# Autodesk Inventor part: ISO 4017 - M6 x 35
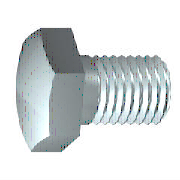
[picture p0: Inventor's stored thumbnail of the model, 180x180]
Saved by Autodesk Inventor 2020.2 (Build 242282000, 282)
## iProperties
Manager: www.cadconsulting.pl
Company: Fabian Stasiak CAD Consulting
Created: 2010-02
Part Number: ISO 4017 - M6 x 35
Material: Stal nierdzewna, 440C
Description: Wkręty z łbem sześciokątnym
Document SubType Name: Modeling
Standard: ISO 4017
Designer: F.Stasiak
Standard Revision: Third edition 1999-08-15
Standards Organization: ISO
Language: pl-PL
Size Designation: M6 x 35
Categories: <MemberInstance><Categories><Category DisplayName="Mocowania" InternalName="e4da775c-781d-43d5-af7c-5136215cf5a6" Mnemonic="FSTN"><Category DisplayName="Śruby"
Density: 7.75 g/cm^3
Appearance: Metal-Stal
IsCustomPart: 0
Author: F.Stasiak
Subject: Zbiór ćwiczeń. Autodesk Inventor 2020. Kurs podstawowy
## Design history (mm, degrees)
sketch "Sketch1"
  geometry: L1 (0, 4.44)-(0, 3); L2 (3, 3)-(35, 3); L3 (35, 3)-(35, 0); L4 (35, 0)-(-0.5, 0); L5 (-7.6, 0)-(42.1, 0) reference; L6 (-0.5, 0)-(-0.5, 4.44); L7 (-0.5, 4.44)-(0, 4.44); L8 (3, 3)-(2.386, 3); L9 (2.386, 3)-(0, 3); L10 (0, -0.888)-(0, 5.328) reference
  constraints: 16 end point, 2 collinear, 2 perpendicular, 1 parallel
  dimensions: "d0" = 35 distance between parallel lines of L3 L1 (= NLG); "d1" = 32 distance from line of L2.start L3 (= GEL); "d2" = 6 diameter of L2 L4 (= GD); "d9" = 0.5001 distance between parallel lines of L6 L1 (computed from SD); "d10" = 8.88 diameter of L7 L4 (= SD2); "d13" = 0.61355 distance of L2.start L8.end (computed from GAL); "d14" = 6 diameter of L9 L4 (= BDM)
revolve "Body" sketch "Sketch1" stored, may be unused: angle "d12" = 90 deg
sketch "Sketch2"
  geometry: L1 (0, 5.774)-(5, 2.887); L2 (5, 2.887)-(5, -2.887); L3 (5, -2.887)-(0, -5.774); L4 (0, -5.774)-(-5, -2.887); L5 (-5, -2.887)-(-5, 2.887); L6 (-5, 2.887)-(0, 5.774); 2 further points
  constraints: 12 end point, 1 coincident, 1 vertical, 11 other
  dimensions: "d11" = 10 distance between parallel lines of L5 L2 (= SW)
extrude "Head" join sketch "Sketch2" distance "d3" = 3.5 (= KOH - SD); taper "d4" = 0 deg
sketch "Sketch4"
  geometry: L1 (-4, 5)-(-4, 5.774); L2 (-4, 5.774)-(-3.554, 5.774); L3 (-3.554, 5.774)-(-4, 5); L4 (-4.7, 0)-(0.2, 0) reference; L5 (-0.5, 5.774)-(-4, 5.774) reference; L6 (-4, 2.887)-(-4, 5.774) reference
  constraints: 6 end point, 2 collinear, 1 perpendicular, 1 vertical
  dimensions: "d5" = 30 deg angle of L3 L1 (= ANG1); "d19" = 10 diameter of L1.start L4 (= SW0)
revolve "Chamfer1" sketch "Sketch4" stored, may be unused: angle "d21" = 90 deg
feature "Thread" dims "d15" = 32 (= GEL), "d16" = 0
chamfer "Chamfer2" distance "d6" = 0.61345 (= -0.5 x SPD + 0.5 x GD); stored, may be unused: second distance "d7" = 0.61355 (computed from GUL), angle "d55" = 45 deg
workplane "Work Plane1"
body "Solid1"
other parameters: "NLG" = 35 [user parameter; used in 1 equation term], "GD" = 6 (= NND) [user parameter; used in 2 equation terms], "BDM" = 6 (= NND) [user parameter; used in 1 equation term], "KOH" = 4 [user parameter; used in 1 equation term], "GEL" = 32 [user parameter; used in 2 equation terms], "SW" = 10 [user parameter; used in 2 equation terms], "SW0" = 10 (= SW) [user parameter; used in 1 equation term], "SPD" = 4.7731 (= NND - 1.2269 x PTC) [user parameter; used in 1 equation term], "SD2" = 8.88 [user parameter; used in 2 equation terms], "SD" = 0.5 [user parameter; used in 2 equation terms], "ANG1" = 30 deg [user parameter; used in 1 equation term], "GAL" = 0.61345 (= 0.61345 x PTC) [user parameter; used in 1 equation term], "GUL" = 0.61345 (= 0.61345 x PTC) [user parameter; used in 1 equation term], "d8" = 0, "RR" = 0.25 [user parameter], "d57" = 0, "d58" = 0, "GD1" = 4.7731 (= THREADDIA - 1.2269 x PTC) [user parameter], "THREADDIA" = 6 [user parameter; used in 1 equation term], "SDH" = 8.88 (= SD2) [user parameter], "SDHG" = 3 [user parameter], "TOA" = 30 deg [user parameter], "PTC" = 1 [user parameter; used in 5 equation terms], "NND" = 6 [user parameter; used in 3 equation terms], "E0" = 11.55 [user parameter]
